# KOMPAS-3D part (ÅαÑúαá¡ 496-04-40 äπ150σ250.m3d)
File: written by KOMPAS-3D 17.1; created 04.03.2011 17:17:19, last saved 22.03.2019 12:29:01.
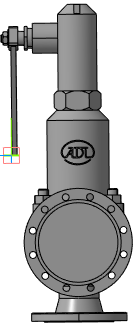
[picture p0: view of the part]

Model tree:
1. Плоскость XY
2. Плоскость ZX
3. Плоскость ZY
4. Ось X
5. Ось Y
6. Ось Z
7. Начало координат
8. Операция без истории:2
